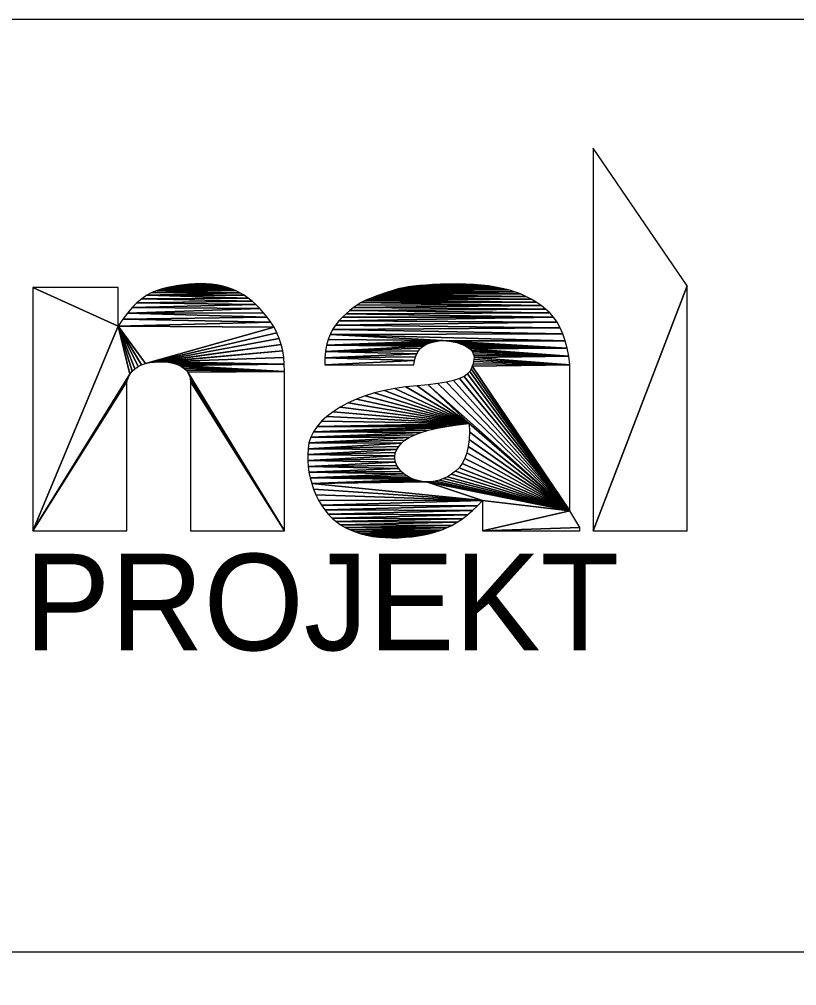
# Model space of a CAD drawing. Extents: x -1442 to 8065, y -772 to 6486.
# Drawn here: x 2249.7 to 2268.23, y 519.2 to 542.23 of the extents above; entities that cross this region are included whole.
import ezdxf

# ---------------------------------------------------------------- set-up
doc = ezdxf.new("R2010")
doc.units = 0
doc.layers.add('Vrstva 1', color=7, linetype='Continuous')

msp = doc.modelspace()

# ---------------------------------------------------------------- linework, layer by layer
for points in [[(2230.002, 542.226), (2395.002, 542.226), (2395.002, 490), (2230.002, 490)], [(2230.002, 542.226), (2395.002, 542.226), (2395.002, 490), (2230.002, 490)], [(2263.382, 539.158), (2263.382, 530.038), (2265.622, 535.878)], [(2252.062, 534.918), (2252.062, 535.838), (2250.022, 535.838)], [(2250.022, 535.838), (2250.022, 530.038), (2252.062, 534.918)], [(2254.856, 535.764), (2252.86, 535.716), (2254.958, 535.712)], [(2252.984, 535.764), (2252.86, 535.716), (2254.856, 535.764)], [(2253.11, 535.802), (2252.984, 535.764), (2254.856, 535.764)], [(2253.236, 535.836), (2253.11, 535.802), (2254.75, 535.808)], [(2254.75, 535.808), (2253.11, 535.802), (2254.856, 535.764)], [(2253.364, 535.864), (2253.236, 535.836), (2254.639, 535.846)], [(2254.639, 535.846), (2253.236, 535.836), (2254.75, 535.808)], [(2253.493, 535.886), (2253.364, 535.864), (2254.524, 535.876)], [(2254.524, 535.876), (2253.364, 535.864), (2254.639, 535.846)], [(2253.623, 535.904), (2253.493, 535.886), (2254.405, 535.9)], [(2254.405, 535.9), (2253.493, 535.886), (2254.524, 535.876)], [(2253.755, 535.918), (2253.623, 535.904), (2254.281, 535.916)], [(2254.281, 535.916), (2253.623, 535.904), (2254.405, 535.9)], [(2253.887, 535.926), (2253.755, 535.918), (2254.281, 535.916)], [(2254.021, 535.928), (2253.887, 535.926), (2254.153, 535.926)], [(2254.153, 535.926), (2253.887, 535.926), (2254.281, 535.916)], [(2258.677, 535.786), (2258.587, 535.76), (2261.36, 535.778)], [(2261.36, 535.778), (2258.587, 535.76), (2261.505, 535.734)], [(2258.765, 535.81), (2258.677, 535.786), (2261.36, 535.778)], [(2258.861, 535.832), (2258.765, 535.81), (2261.208, 535.816)], [(2261.208, 535.816), (2258.765, 535.81), (2261.36, 535.778)], [(2258.972, 535.85), (2258.861, 535.832), (2261.049, 535.848)], [(2261.049, 535.848), (2258.861, 535.832), (2261.208, 535.816)], [(2259.097, 535.868), (2258.972, 535.85), (2261.049, 535.848)], [(2259.236, 535.882), (2259.097, 535.868), (2260.883, 535.874)], [(2260.883, 535.874), (2259.097, 535.868), (2261.049, 535.848)], [(2259.391, 535.896), (2259.236, 535.882), (2260.709, 535.894)], [(2260.709, 535.894), (2259.236, 535.882), (2260.883, 535.874)], [(2259.56, 535.906), (2259.391, 535.896), (2260.709, 535.894)], [(2259.744, 535.914), (2259.56, 535.906), (2260.528, 535.91)], [(2260.528, 535.91), (2259.56, 535.906), (2260.709, 535.894)], [(2259.943, 535.92), (2259.744, 535.914), (2260.341, 535.918)], [(2260.341, 535.918), (2259.744, 535.914), (2260.528, 535.91)], [(2260.145, 535.922), (2259.943, 535.92), (2260.341, 535.918)], [(2265.622, 535.878), (2263.382, 530.038), (2265.622, 530.038)], [(2252.62, 535.57), (2252.504, 535.472), (2255.25, 535.512)], [(2252.739, 535.652), (2252.62, 535.57), (2255.155, 535.586)], [(2255.155, 535.586), (2252.62, 535.57), (2255.25, 535.512)], [(2252.86, 535.716), (2252.739, 535.652), (2254.958, 535.712)], [(2254.958, 535.712), (2252.739, 535.652), (2255.058, 535.654)], [(2255.058, 535.654), (2252.739, 535.652), (2255.155, 535.586)], [(2258.037, 535.566), (2257.944, 535.524), (2261.902, 535.558)], [(2261.902, 535.558), (2257.944, 535.524), (2262.022, 535.486)], [(2258.131, 535.602), (2258.037, 535.566), (2261.902, 535.558)], [(2258.223, 535.638), (2258.131, 535.602), (2261.776, 535.624)], [(2261.776, 535.624), (2258.131, 535.602), (2261.902, 535.558)], [(2258.315, 535.672), (2258.223, 535.638), (2261.776, 535.624)], [(2258.407, 535.702), (2258.315, 535.672), (2261.644, 535.682)], [(2261.644, 535.682), (2258.315, 535.672), (2261.776, 535.624)], [(2258.497, 535.732), (2258.407, 535.702), (2261.644, 535.682)], [(2258.587, 535.76), (2258.497, 535.732), (2261.505, 535.734)], [(2261.505, 535.734), (2258.497, 535.732), (2261.644, 535.682)], [(2252.39, 535.358), (2252.278, 535.228), (2255.434, 535.336)], [(2255.434, 535.336), (2252.278, 535.228), (2255.523, 535.236)], [(2252.504, 535.472), (2252.39, 535.358), (2255.343, 535.428)], [(2255.343, 535.428), (2252.39, 535.358), (2255.434, 535.336)], [(2255.25, 535.512), (2252.504, 535.472), (2255.343, 535.428)], [(2257.67, 535.358), (2257.581, 535.288), (2262.243, 535.322)], [(2262.243, 535.322), (2257.581, 535.288), (2262.344, 535.23)], [(2257.76, 535.42), (2257.67, 535.358), (2262.136, 535.408)], [(2262.136, 535.408), (2257.67, 535.358), (2262.243, 535.322)], [(2257.852, 535.476), (2257.76, 535.42), (2262.136, 535.408)], [(2257.944, 535.524), (2257.852, 535.476), (2262.022, 535.486)], [(2262.022, 535.486), (2257.852, 535.476), (2262.136, 535.408)], [(2252.169, 535.082), (2252.062, 534.918), (2255.694, 535.012)], [(2252.278, 535.228), (2252.169, 535.082), (2255.609, 535.128)], [(2255.609, 535.128), (2252.169, 535.082), (2255.694, 535.012)], [(2255.523, 535.236), (2252.278, 535.228), (2255.609, 535.128)], [(2257.406, 535.13), (2257.32, 535.04), (2262.437, 535.126)], [(2262.437, 535.126), (2257.32, 535.04), (2262.521, 535.008)], [(2257.493, 535.212), (2257.406, 535.13), (2262.437, 535.126)], [(2257.581, 535.288), (2257.493, 535.212), (2262.344, 535.23)], [(2262.344, 535.23), (2257.493, 535.212), (2262.437, 535.126)], [(2252.062, 534.918), (2250.022, 530.038), (2252.34, 533.77)], [(2255.694, 535.012), (2252.062, 534.918), (2255.773, 534.888)], [(2252.062, 534.918), (2252.711, 534.024), (2255.773, 534.888)], [(2252.062, 534.918), (2252.617, 533.994), (2252.711, 534.024)], [(2252.062, 534.918), (2252.533, 533.952), (2252.617, 533.994)], [(2252.062, 534.918), (2252.459, 533.902), (2252.533, 533.952)], [(2252.062, 534.918), (2252.395, 533.84), (2252.459, 533.902)], [(2252.062, 534.918), (2252.34, 533.77), (2252.395, 533.84)], [(2255.773, 534.888), (2252.711, 534.024), (2255.841, 534.758)], [(2257.239, 534.942), (2257.17, 534.836), (2262.595, 534.876)], [(2262.595, 534.876), (2257.17, 534.836), (2262.659, 534.73)], [(2257.32, 535.04), (2257.239, 534.942), (2262.521, 535.008)], [(2262.521, 535.008), (2257.239, 534.942), (2262.595, 534.876)], [(2255.841, 534.758), (2252.711, 534.024), (2252.815, 534.046)], [(2255.841, 534.758), (2252.815, 534.046), (2255.898, 534.622)], [(2255.898, 534.622), (2252.815, 534.046), (2255.944, 534.478)], [(2257.112, 534.72), (2257.064, 534.594), (2259.793, 534.57)], [(2257.17, 534.836), (2257.112, 534.72), (2262.659, 534.73)], [(2262.659, 534.73), (2257.112, 534.72), (2262.714, 534.568)], [(2257.112, 534.72), (2259.793, 534.57), (2262.714, 534.568)], [(2255.944, 534.478), (2252.815, 534.046), (2252.921, 534.058)], [(2255.944, 534.478), (2252.921, 534.058), (2255.98, 534.328)], [(2257.027, 534.46), (2257.001, 534.314), (2259.324, 534.438)], [(2259.324, 534.438), (2257.001, 534.314), (2259.265, 534.388)], [(2259.265, 534.388), (2257.001, 534.314), (2259.215, 534.328)], [(2257.064, 534.594), (2257.027, 534.46), (2259.793, 534.57)], [(2259.793, 534.57), (2257.027, 534.46), (2259.711, 534.566)], [(2259.711, 534.566), (2257.027, 534.46), (2259.629, 534.554)], [(2259.629, 534.554), (2257.027, 534.46), (2259.548, 534.536)], [(2259.548, 534.536), (2257.027, 534.46), (2259.467, 534.512)], [(2259.467, 534.512), (2257.027, 534.46), (2259.391, 534.48)], [(2259.391, 534.48), (2257.027, 534.46), (2259.324, 534.438)], [(2259.793, 534.57), (2259.875, 534.568), (2262.714, 534.568)], [(2259.875, 534.568), (2259.958, 534.56), (2262.714, 534.568)], [(2262.714, 534.568), (2259.958, 534.56), (2262.759, 534.392)], [(2259.958, 534.56), (2260.042, 534.546), (2262.759, 534.392)], [(2260.042, 534.546), (2260.126, 534.524), (2262.759, 534.392)], [(2260.126, 534.524), (2260.206, 534.498), (2262.759, 534.392)], [(2260.206, 534.498), (2260.278, 534.47), (2262.759, 534.392)], [(2260.278, 534.47), (2260.34, 534.44), (2262.759, 534.392)], [(2260.34, 534.44), (2260.394, 534.408), (2262.759, 534.392)], [(2260.394, 534.408), (2260.439, 534.374), (2262.759, 534.392)], [(2262.759, 534.392), (2260.439, 534.374), (2262.795, 534.202)], [(2255.98, 534.328), (2252.921, 534.058), (2253.022, 534.066)], [(2255.98, 534.328), (2253.022, 534.066), (2253.117, 534.066)], [(2255.98, 534.328), (2253.117, 534.066), (2256.004, 534.17)], [(2256.004, 534.17), (2253.117, 534.066), (2256.018, 534.008)], [(2256.986, 534.16), (2256.982, 533.998), (2259.117, 534.094)], [(2257.001, 534.314), (2256.986, 534.16), (2259.174, 534.26)], [(2259.174, 534.26), (2256.986, 534.16), (2259.141, 534.182)], [(2259.141, 534.182), (2256.986, 534.16), (2259.117, 534.094)], [(2259.215, 534.328), (2257.001, 534.314), (2259.174, 534.26)], [(2260.439, 534.374), (2260.476, 534.338), (2262.795, 534.202)], [(2260.476, 534.338), (2260.503, 534.3), (2262.795, 534.202)], [(2260.503, 534.3), (2260.522, 534.26), (2262.795, 534.202)], [(2260.522, 534.26), (2260.534, 534.216), (2262.795, 534.202)], [(2260.534, 534.216), (2260.539, 534.17), (2262.795, 534.202)], [(2260.539, 534.17), (2260.538, 534.122), (2262.822, 533.998)], [(2262.795, 534.202), (2260.539, 534.17), (2262.822, 533.998)], [(2253.117, 534.066), (2253.208, 534.062), (2256.018, 534.008)], [(2253.208, 534.062), (2253.293, 534.05), (2256.018, 534.008)], [(2253.293, 534.05), (2253.372, 534.032), (2256.018, 534.008)], [(2253.372, 534.032), (2253.447, 534.008), (2256.018, 534.008)], [(2253.447, 534.008), (2253.516, 533.978), (2256.018, 534.008)], [(2256.018, 534.008), (2253.516, 533.978), (2256.022, 533.838)], [(2253.516, 533.978), (2253.578, 533.944), (2256.022, 533.838)], [(2253.578, 533.944), (2253.632, 533.906), (2256.022, 533.838)], [(2259.117, 534.094), (2256.982, 533.998), (2259.102, 533.998)], [(2260.496, 533.96), (2260.47, 533.9), (2262.822, 530.518)], [(2260.516, 534.016), (2260.496, 533.96), (2262.822, 533.998)], [(2262.822, 533.998), (2260.496, 533.96), (2262.822, 530.518)], [(2260.53, 534.07), (2260.516, 534.016), (2262.822, 533.998)], [(2260.538, 534.122), (2260.53, 534.07), (2262.822, 533.998)], [(2252.34, 533.77), (2250.022, 530.038), (2252.296, 533.688)], [(2253.632, 533.906), (2253.678, 533.864), (2256.022, 533.838)], [(2253.678, 533.864), (2253.715, 533.818), (2256.022, 533.838)], [(2256.022, 533.838), (2253.715, 533.818), (2256.022, 530.038)], [(2253.715, 533.818), (2253.744, 533.768), (2256.022, 530.038)], [(2253.744, 533.768), (2253.765, 533.716), (2256.022, 530.038)], [(2253.765, 533.716), (2253.777, 533.658), (2256.022, 530.038)], [(2260.306, 533.72), (2260.195, 533.67), (2262.822, 530.518)], [(2260.387, 533.776), (2260.306, 533.72), (2262.822, 530.518)], [(2260.438, 533.838), (2260.387, 533.776), (2262.822, 530.518)], [(2260.47, 533.9), (2260.438, 533.838), (2262.822, 530.518)], [(2252.296, 533.688), (2250.022, 530.038), (2252.262, 533.598)], [(2252.262, 533.598), (2250.022, 530.038), (2252.262, 530.038)], [(2253.777, 533.658), (2253.782, 533.598), (2256.022, 530.038)], [(2253.782, 533.598), (2253.782, 530.038), (2256.022, 530.038)], [(2258.911, 533.468), (2258.652, 533.432), (2260.426, 532.594)], [(2259.183, 533.496), (2258.911, 533.468), (2260.426, 532.594)], [(2259.446, 533.52), (2259.183, 533.496), (2260.426, 532.594)], [(2259.679, 533.55), (2259.446, 533.52), (2262.822, 530.518)], [(2259.446, 533.52), (2260.426, 532.594), (2262.822, 530.518)], [(2259.881, 533.584), (2259.679, 533.55), (2262.822, 530.518)], [(2260.053, 533.624), (2259.881, 533.584), (2262.822, 530.518)], [(2260.195, 533.67), (2260.053, 533.624), (2262.822, 530.518)], [(2257.947, 533.256), (2257.736, 533.176), (2260.426, 532.594)], [(2258.169, 533.326), (2257.947, 533.256), (2260.426, 532.594)], [(2258.404, 533.384), (2258.169, 533.326), (2260.426, 532.594)], [(2258.652, 533.432), (2258.404, 533.384), (2260.426, 532.594)], [(2257.538, 533.086), (2257.352, 532.986), (2260.426, 532.594)], [(2257.736, 533.176), (2257.538, 533.086), (2260.426, 532.594)], [(2257.183, 532.878), (2257.035, 532.766), (2260.426, 532.594)], [(2257.352, 532.986), (2257.183, 532.878), (2260.426, 532.594)], [(2256.907, 532.648), (2256.801, 532.526), (2260.426, 532.594)], [(2260.426, 532.594), (2256.801, 532.526), (2260.147, 532.562)], [(2260.147, 532.562), (2256.801, 532.526), (2259.892, 532.526)], [(2257.035, 532.766), (2256.907, 532.648), (2260.426, 532.594)], [(2260.426, 532.594), (2260.431, 532.394), (2262.822, 530.518)], [(2256.715, 532.4), (2256.65, 532.27), (2259.279, 532.384)], [(2259.279, 532.384), (2256.65, 532.27), (2259.126, 532.326)], [(2259.126, 532.326), (2256.65, 532.27), (2258.997, 532.264)], [(2259.892, 532.526), (2256.715, 532.4), (2259.663, 532.484)], [(2256.801, 532.526), (2256.715, 532.4), (2259.892, 532.526)], [(2259.663, 532.484), (2256.715, 532.4), (2259.458, 532.436)], [(2259.458, 532.436), (2256.715, 532.4), (2259.279, 532.384)], [(2260.431, 532.394), (2260.422, 532.212), (2262.822, 530.518)], [(2256.606, 532.134), (2256.583, 531.994), (2258.811, 532.124)], [(2258.811, 532.124), (2256.583, 531.994), (2258.745, 532.052)], [(2256.65, 532.27), (2256.606, 532.134), (2258.997, 532.264)], [(2258.997, 532.264), (2256.606, 532.134), (2258.894, 532.196)], [(2258.894, 532.196), (2256.606, 532.134), (2258.811, 532.124)], [(2260.422, 532.212), (2260.4, 532.046), (2262.822, 530.518)], [(2256.583, 531.994), (2256.575, 531.854), (2258.696, 531.978)], [(2258.696, 531.978), (2256.575, 531.854), (2258.664, 531.904)], [(2258.664, 531.904), (2256.575, 531.854), (2258.648, 531.828)], [(2256.575, 531.854), (2256.576, 531.714), (2258.648, 531.828)], [(2258.745, 532.052), (2256.583, 531.994), (2258.696, 531.978)], [(2260.366, 531.898), (2260.318, 531.764), (2262.822, 530.518)], [(2260.4, 532.046), (2260.366, 531.898), (2262.822, 530.518)], [(2258.648, 531.828), (2256.576, 531.714), (2258.649, 531.752)], [(2258.649, 531.752), (2256.576, 531.714), (2258.667, 531.676)], [(2256.576, 531.714), (2256.586, 531.574), (2258.667, 531.676)], [(2258.667, 531.676), (2256.586, 531.574), (2258.701, 531.598)], [(2260.258, 531.646), (2260.184, 531.544), (2262.822, 530.518)], [(2260.318, 531.764), (2260.258, 531.646), (2262.822, 530.518)], [(2258.701, 531.598), (2256.586, 531.574), (2258.748, 531.524)], [(2256.586, 531.574), (2256.605, 531.436), (2258.748, 531.524)], [(2258.748, 531.524), (2256.605, 531.436), (2258.803, 531.456)], [(2258.803, 531.456), (2256.605, 531.436), (2258.866, 531.398)], [(2256.605, 531.436), (2256.633, 531.3), (2258.866, 531.398)], [(2258.866, 531.398), (2256.633, 531.3), (2258.937, 531.346)], [(2260.005, 531.388), (2259.909, 531.328), (2262.822, 530.518)], [(2260.098, 531.46), (2260.005, 531.388), (2262.822, 530.518)], [(2260.184, 531.544), (2260.098, 531.46), (2262.822, 530.518)], [(2258.937, 531.346), (2256.633, 531.3), (2259.016, 531.302)], [(2259.016, 531.302), (2256.633, 531.3), (2259.102, 531.266)], [(2256.633, 531.3), (2256.67, 531.164), (2259.102, 531.266)], [(2259.102, 531.266), (2256.67, 531.164), (2259.197, 531.238)], [(2259.197, 531.238), (2256.67, 531.164), (2259.3, 531.218)], [(2259.3, 531.218), (2256.67, 531.164), (2259.406, 531.208)], [(2259.406, 531.208), (2256.67, 531.164), (2260.742, 530.758)], [(2256.67, 531.164), (2256.716, 531.03), (2260.742, 530.758)], [(2259.406, 531.208), (2260.742, 530.758), (2262.822, 530.518)], [(2259.51, 531.208), (2259.406, 531.208), (2262.822, 530.518)], [(2259.613, 531.22), (2259.51, 531.208), (2262.822, 530.518)], [(2259.713, 531.246), (2259.613, 531.22), (2262.822, 530.518)], [(2259.812, 531.282), (2259.713, 531.246), (2262.822, 530.518)], [(2259.909, 531.328), (2259.812, 531.282), (2262.822, 530.518)], [(2256.716, 531.03), (2256.771, 530.896), (2260.742, 530.758)], [(2256.771, 530.896), (2256.834, 530.768), (2260.742, 530.758)], [(2256.834, 530.768), (2256.904, 530.65), (2260.742, 530.758)], [(2260.742, 530.758), (2256.904, 530.65), (2260.624, 530.634)], [(2260.742, 530.758), (2260.742, 530.038), (2262.822, 530.518)], [(2256.904, 530.65), (2256.981, 530.538), (2260.624, 530.634)], [(2260.624, 530.634), (2256.981, 530.538), (2260.506, 530.52)], [(2256.981, 530.538), (2257.065, 530.438), (2260.506, 530.52)], [(2260.506, 530.52), (2257.065, 530.438), (2260.385, 530.418)], [(2262.822, 530.518), (2260.742, 530.038), (2263.062, 530.118)], [(2257.065, 530.438), (2257.155, 530.344), (2260.385, 530.418)], [(2260.385, 530.418), (2257.155, 530.344), (2260.263, 530.324)], [(2257.155, 530.344), (2257.253, 530.26), (2260.263, 530.324)], [(2260.263, 530.324), (2257.253, 530.26), (2260.139, 530.242)], [(2257.253, 530.26), (2257.357, 530.186), (2260.139, 530.242)], [(2260.139, 530.242), (2257.357, 530.186), (2260.014, 530.17)], [(2257.357, 530.186), (2257.469, 530.12), (2260.014, 530.17)], [(2260.014, 530.17), (2257.469, 530.12), (2259.887, 530.108)], [(2257.469, 530.12), (2257.587, 530.062), (2259.887, 530.108)], [(2259.887, 530.108), (2257.587, 530.062), (2259.758, 530.058)], [(2257.587, 530.062), (2257.711, 530.012), (2259.758, 530.058)], [(2259.758, 530.058), (2257.711, 530.012), (2259.627, 530.014)], [(2259.627, 530.014), (2257.711, 530.012), (2259.491, 529.976)], [(2257.711, 530.012), (2257.841, 529.97), (2259.491, 529.976)], [(2263.062, 530.118), (2260.742, 530.038), (2263.062, 530.038)], [(2259.491, 529.976), (2257.841, 529.97), (2259.35, 529.946)], [(2257.841, 529.97), (2257.978, 529.936), (2259.35, 529.946)], [(2259.35, 529.946), (2257.978, 529.936), (2259.206, 529.92)], [(2257.978, 529.936), (2258.12, 529.908), (2259.206, 529.92)], [(2259.206, 529.92), (2258.12, 529.908), (2259.057, 529.9)], [(2258.12, 529.908), (2258.269, 529.888), (2259.057, 529.9)], [(2259.057, 529.9), (2258.269, 529.888), (2258.904, 529.886)], [(2258.269, 529.888), (2258.423, 529.878), (2258.904, 529.886)], [(2258.904, 529.886), (2258.423, 529.878), (2258.746, 529.876)], [(2258.423, 529.878), (2258.584, 529.874), (2258.746, 529.876)]]:
    msp.add_lwpolyline(points, close=True)
at = {"layer": 'Vrstva 1'}
msp.add_line((2345.002, 520), (2230.002, 520), dxfattribs=at)

# ---------------------------------------------------------------- texts
msp.add_text('PROJEKT', height=2.299).set_placement((2249.822, 527.194))

doc.saveas('drawing.dxf')
